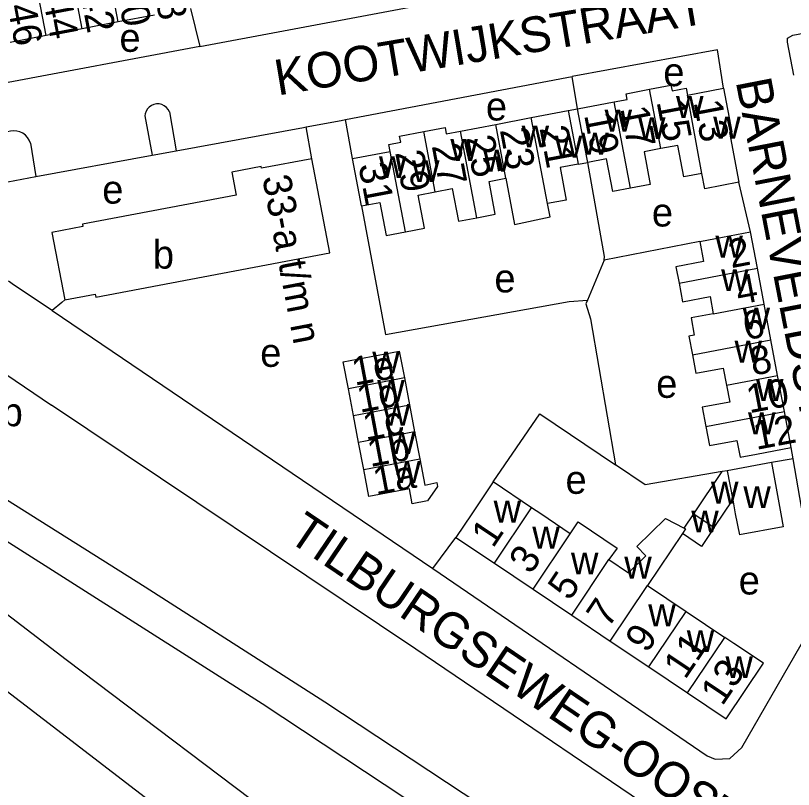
# Model space of a CAD drawing. Extents: x 158356 to 159894, y 383831 to 385260.
# Drawn here: x 158701.2 to 158810.6, y 383961.2 to 384070.1 of the extents above; entities that cross this region are included whole.
import ezdxf

# ---------------------------------------------------------------- set-up
doc = ezdxf.new("R2010")
doc.units = 0
for name, color, linetype in [('BLT_Basislijn', 7, 'Continuous'), ('BLT_Bebouwing', 7, 'Continuous'), ('BLT_Centroide', 7, 'Continuous'), ('BLT_Huisnummer', 7, 'Continuous'), ('BLT_Huisnummer_ tussenligend', 7, 'Continuous'), ('BLT_Huisnummer_reeks', 7, 'Continuous'), ('BLT_Onderdoorgang_en_onderverdeling', 7, 'Continuous'), ('BLT_Onderverdeling_panden', 7, 'Continuous'), ('BLT_Straatnaam', 7, 'Continuous')]:
    doc.layers.add(name, color=color, linetype=linetype)

msp = doc.modelspace()

# ---------------------------------------------------------------- linework, layer by layer
at = {"layer": 'BLT_Basislijn'}
for p, q in [((158727.11, 384065.73), (158770.26, 384073.85)), ((158725.81, 384071.1), (158727.11, 384065.73)), ((158727.11, 384065.73), (158694.69, 384059.64)), ((158780.27, 384056.96), (158779.51, 384061.52)), ((158722.83, 384056.55), (158723.81, 384051.07)), ((158719.39, 384056), (158720.43, 384050.45)), ((158748.6, 384049.99), (158747.61, 384055.47)), ((158742.89, 384049.96), (158742.08, 384054.43)), ((158703.31, 384052.16), (158704.05, 384047.44)), ((158720.43, 384050.45), (158723.81, 384051.07)), ((158704.05, 384047.44), (158720.43, 384050.45)), ((158699.14, 384046.54), (158704.05, 384047.44)), ((158804.58, 384039.65), (158802.96, 384046.65)), ((158797.44, 384038.29), (158783.99, 384035.69)), ((158783.99, 384035.69), (158781.64, 384030.04)), ((158677.95, 384034.41), (158706.27, 384015.3)), ((158706.34, 384028.61), (158759.91, 383992.3)), ((158719.42, 383989.69), (158667.79, 384022.18)), ((158733.69, 383949.17), (158656.47, 384008.34)), ((158810.59, 384007.75), (158810.32, 384009.33)), ((158810.59, 384007.75), (158807.52, 384007.22)), ((158813.96, 383988.01), (158810.59, 384007.75)), ((158789.78, 384004.07), (158785.59, 384006.9)), ((158800.61, 384005.94), (158789.78, 384004.07)), ((158759.91, 383992.3), (158763.12, 383996.69))]:
    msp.add_line(p, q, dxfattribs=at)
for points in [[(158810.66, 384061.72), (158809.81, 384066.33), (158809.81, 384066.91), (158810.54, 384067.32), (158847.76, 384074.35)], [(158800.8, 384059.86), (158799.92, 384065.26), (158779.51, 384061.52)], [(158747.61, 384055.47), (158778.74, 384061.38), (158779.51, 384061.52)], [(158722.83, 384056.55), (158722.65, 384056.88), (158722.41, 384057.17), (158722.11, 384057.4), (158721.77, 384057.57), (158721.4, 384057.66), (158721.03, 384057.67), (158720.65, 384057.6), (158720.31, 384057.45), (158720, 384057.23), (158719.74, 384056.96), (158719.55, 384056.63), (158719.43, 384056.28), (158719.39, 384056)], [(158742.08, 384054.43), (158746.98, 384055.34), (158747.61, 384055.47)], [(158723.81, 384051.07), (158741.69, 384054.36), (158742.08, 384054.43)], [(158703.31, 384052.16), (158703.13, 384052.57), (158702.88, 384052.95), (158702.57, 384053.27), (158702.21, 384053.53), (158701.81, 384053.73), (158701.38, 384053.85), (158700.93, 384053.89), (158700.48, 384053.85), (158700.05, 384053.73), (158699.65, 384053.54), (158699.28, 384053.28), (158698.97, 384052.96), (158698.72, 384052.58), (158698.54, 384052.17), (158698.44, 384051.74), (158698.42, 384051.29), (158698.46, 384050.9)], [(158783.99, 384035.69), (158784.03, 384036.22), (158781.7, 384049.42)], [(158749.86, 384043.31), (158753.23, 384025.24), (158779.09, 384029.87), (158781.64, 384030.04)], [(158706.34, 384028.61), (158701.03, 384032.11), (158700.18, 384032.75)], [(158708.12, 384030.1), (158707.7, 384029.75), (158706.34, 384028.61)], [(158781.64, 384030.04), (158781.43, 384029.54), (158782.1, 384027.44), (158785.59, 384006.9)], [(158735.9, 383973.27), (158664.77, 384018.5)], [(158658.2, 384017.9), (158708.3, 383979.52), (158740.71, 383955.02), (158752.16, 383946.49), (158811.09, 383902.1)], [(158845.77, 383924.27), (158815.12, 383942.93), (158798.74, 383953.03), (158757.49, 383980.97), (158706.27, 384015.3)], [(158768.38, 384004.49), (158774.94, 384014.07), (158785.59, 384006.9)], [(158759.91, 383992.3), (158798.47, 383965.97), (158799.62, 383965.5), (158801.69, 383965.58), (158803.35, 383967.13), (158814.2, 383985.93), (158813.96, 383988.01)], [(158848.65, 383902.86), (158801.74, 383935.63), (158773.98, 383954.21), (158744.72, 383973.5), (158719.42, 383989.69)], [(158848.91, 383896.59), (158784.62, 383941.05), (158735.9, 383973.27)]]:
    msp.add_lwpolyline(points, dxfattribs=at)
at = {"layer": 'BLT_Bebouwing'}
for p, q in [((158720.73, 384070.15), (158715.65, 384069.19)), ((158715.65, 384069.19), (158710.58, 384068.23)), ((158710.58, 384068.23), (158705.5, 384067.27)), ((158705.5, 384067.27), (158700.42, 384066.32)), ((158795.73, 384058.9), (158800.8, 384059.86)), ((158780.27, 384056.96), (158785.42, 384057.94)), ((158773.74, 384055.74), (158778.93, 384056.72)), ((158778.93, 384056.72), (158780.27, 384056.96)), ((158768.74, 384054.79), (158773.74, 384055.74)), ((158763.77, 384053.85), (158768.74, 384054.79)), ((158753.89, 384050.99), (158753.7, 384051.96)), ((158745.39, 384036.7), (158742.89, 384049.96)), ((158748.6, 384049.99), (158753.89, 384050.99)), ((158780.36, 384049.2), (158781.7, 384049.42)), ((158805.55, 384034.55), (158804.58, 384039.65)), ((158806.5, 384029.51), (158805.55, 384034.55)), ((158807.46, 384024.47), (158806.5, 384029.51)), ((158808.4, 384019.47), (158807.46, 384024.47)), ((158809.37, 384014.39), (158808.4, 384019.47)), ((158755.89, 384019.12), (158756.61, 384015.32)), ((158748.73, 384013.82), (158748.01, 384017.61)), ((158756.61, 384015.32), (158757.33, 384011.53)), ((158749.46, 384010.03), (158748.73, 384013.82)), ((158810.32, 384009.33), (158809.37, 384014.39)), ((158757.33, 384011.53), (158758.05, 384007.73)), ((158750.18, 384006.23), (158749.46, 384010.03)), ((158807.52, 384007.22), (158801.32, 384006.06)), ((158796.63, 384000), (158800.61, 384005.94)), ((158801.32, 384006.06), (158800.61, 384005.94)), ((158773.8, 384000.86), (158768.38, 384004.49)), ((158799.48, 383998.1), (158802.08, 384001.98)), ((158795.27, 383997.97), (158796.63, 384000)), ((158763.12, 383996.69), (158768.56, 383993.05)), ((158768.56, 383993.05), (158773.99, 383989.4)), ((158790.1, 383989.92), (158795.53, 383986.28)), ((158773.99, 383989.4), (158779.43, 383985.76)), ((158779.43, 383985.76), (158784.86, 383982.11)), ((158795.53, 383986.28), (158800.97, 383982.63)), ((158784.86, 383982.11), (158790.3, 383978.47)), ((158790.3, 383978.47), (158795.73, 383974.82))]:
    msp.add_line(p, q, dxfattribs=at)
for points in [[(158790.4, 384059.73), (158793.4, 384060.3), (158793.55, 384059.5), (158795.54, 384059.88), (158795.73, 384058.9)], [(158800.8, 384059.86), (158801.96, 384053.72), (158801.64, 384053.66), (158802.96, 384046.65)], [(158785.42, 384057.94), (158787.24, 384058.28), (158787.09, 384059.1), (158790.4, 384059.73)], [(158758.62, 384053.78), (158761.61, 384054.34), (158761.77, 384053.48), (158763.77, 384053.85)], [(158753.7, 384051.96), (158755.38, 384052.27), (158755.21, 384053.13), (158758.62, 384053.78)], [(158791.98, 384051.39), (158789.62, 384050.94), (158790.49, 384046.35), (158787.72, 384045.82)], [(158797.75, 384047.88), (158795.19, 384047.39), (158794.35, 384051.84), (158791.98, 384051.39)], [(158742.89, 384049.96), (158735.79, 384048.61), (158735.75, 384048.84), (158731.64, 384048.06), (158732.24, 384044.85), (158710.59, 384040.75), (158710.65, 384040.42), (158706.32, 384039.6), (158708.12, 384030.1)], [(158749.86, 384043.31), (158749.53, 384045.07), (158748.6, 384049.99)], [(158787.72, 384045.82), (158785.22, 384045.35), (158784.35, 384049.92), (158781.7, 384049.42)], [(158780.36, 384049.2), (158777.8, 384048.71), (158778.66, 384044.14), (158776.03, 384043.64)], [(158802.96, 384046.65), (158798.15, 384045.74), (158797.75, 384047.88)], [(158766.08, 384041.65), (158768.68, 384042.14), (158767.81, 384046.75), (158770.17, 384047.2)], [(158770.17, 384047.2), (158771.39, 384040.71), (158776.42, 384041.76), (158776.03, 384043.64)], [(158760.23, 384045.3), (158762.62, 384045.76), (158763.49, 384041.16), (158766.08, 384041.65)], [(158756.03, 384039.68), (158758.72, 384040.19), (158757.84, 384044.85), (158760.23, 384045.3)], [(158749.86, 384043.31), (158752.46, 384043.8), (158753.33, 384039.17), (158756.03, 384039.68)], [(158797.44, 384038.29), (158799.67, 384038.72), (158804.58, 384039.65)], [(158797.44, 384038.29), (158797.97, 384035.49), (158794.09, 384034.76), (158794.53, 384032.46)], [(158708.12, 384030.1), (158712.4, 384030.91), (158712.48, 384030.47), (158745.39, 384036.7)], [(158794.53, 384032.46), (158795.02, 384029.85), (158798.89, 384030.58), (158799.35, 384028.15)], [(158799.35, 384028.15), (158796.22, 384027.56), (158796.68, 384025.14), (158795.92, 384024.99), (158796.41, 384022.39)], [(158748.01, 384017.61), (158747.28, 384021.41), (158755.17, 384022.91), (158755.89, 384019.12)], [(158796.41, 384022.39), (158796.91, 384019.78), (158800.76, 384020.51), (158801.21, 384018.11)], [(158801.21, 384018.11), (158801.67, 384015.72), (158797.8, 384014.99), (158798.31, 384012.3)], [(158798.31, 384012.3), (158798.82, 384009.6), (158802.67, 384010.33), (158803.12, 384007.97), (158805.41, 384008.41), (158810.32, 384009.33)], [(158758.05, 384007.73), (158758.75, 384004.06), (158760.45, 384004.4), (158760.55, 384003.87), (158759.15, 384001.82), (158757.01, 384001.4), (158756.6, 384003.52), (158750.91, 384002.44), (158750.18, 384006.23)], [(158807.52, 384007.22), (158808.87, 384000.01), (158809.2, 383998.18), (158803.05, 383997.04)], [(158768.38, 384004.49), (158765.93, 384000.83), (158765.36, 383999.99), (158763.12, 383996.69)], [(158802.08, 384001.98), (158802.45, 384000), (158803.05, 383997.04)], [(158779.23, 383997.21), (158775.08, 384000), (158773.8, 384000.86)], [(158779.23, 383997.21), (158780.32, 383998.86), (158785.83, 383995.2), (158784.67, 383993.57)], [(158784.67, 383993.57), (158787.42, 383991.7), (158789.87, 383994.11), (158788.61, 383995.39), (158792.62, 383999.33), (158795.27, 383997.97)], [(158799.48, 383998.1), (158797.68, 383995.43), (158795, 383997.22)], [(158795, 383997.22), (158790.1, 383989.92)], [(158795.73, 383974.82), (158801.17, 383971.17), (158806.4, 383978.98), (158802.25, 383981.77), (158800.97, 383982.63)]]:
    msp.add_lwpolyline(points, dxfattribs=at)
at = {"layer": 'BLT_Onderdoorgang_en_onderverdeling'}
for points in [[(158778.93, 384056.72), (158779.86, 384051.81), (158780.36, 384049.2)], [(158781.7, 384049.42), (158781.2, 384052.05), (158780.27, 384056.96)]]:
    msp.add_lwpolyline(points, dxfattribs=at)
at = {"layer": 'BLT_Onderverdeling_panden'}
for p, q in [((158710.58, 384068.23), (158708.35, 384080.01)), ((158715.65, 384069.19), (158714.28, 384076.26)), ((158705.5, 384067.27), (158704.16, 384074.35)), ((158791.98, 384051.39), (158790.4, 384059.73)), ((158787.72, 384045.82), (158785.42, 384057.94)), ((158776.03, 384043.64), (158773.74, 384055.74)), ((158770.17, 384047.2), (158768.74, 384054.79)), ((158760.23, 384045.3), (158758.62, 384053.78)), ((158766.08, 384041.65), (158763.77, 384053.85)), ((158756.03, 384039.68), (158753.89, 384050.99)), ((158794.53, 384032.46), (158805.55, 384034.55)), ((158799.35, 384028.15), (158806.5, 384029.51)), ((158796.41, 384022.39), (158807.46, 384024.47)), ((158801.21, 384018.11), (158808.4, 384019.47)), ((158755.89, 384019.12), (158748.01, 384017.61)), ((158748.73, 384013.82), (158756.61, 384015.32)), ((158798.31, 384012.3), (158809.37, 384014.39)), ((158757.33, 384011.53), (158749.46, 384010.03)), ((158750.18, 384006.23), (158758.05, 384007.73)), ((158801.32, 384006.06), (158802.08, 384001.98)), ((158768.56, 383993.05), (158773.8, 384000.86)), ((158796.63, 384000), (158799.48, 383998.1)), ((158773.99, 383989.4), (158779.23, 383997.21)), ((158779.43, 383985.76), (158784.67, 383993.57)), ((158784.86, 383982.11), (158790.1, 383989.92)), ((158790.3, 383978.47), (158795.53, 383986.28)), ((158795.73, 383974.82), (158800.97, 383982.63))]:
    msp.add_line(p, q, dxfattribs=at)
for points in [[(158797.75, 384047.88), (158795.73, 384058.9)], [(158795.27, 383997.97), (158795.44, 383997.88), (158795, 383997.22)]]:
    msp.add_lwpolyline(points, dxfattribs=at)

# ---------------------------------------------------------------- texts
at = {"layer": 'BLT_Centroide'}
for s, p in [('e', (158715.81, 384064.99)), ('e', (158792.32, 384060.16)), ('w', (158794.11, 384055.69)), ('e', (158767.36, 384055.33)), ('w', (158784.06, 384053.78)), ('w', (158788.77, 384052.73)), ('w', (158799.34, 384052.78)), ('w', (158772.39, 384051.55)), ('w', (158777.05, 384050.11)), ('w', (158780.77, 384050.53)), ('w', (158762.36, 384049.66)), ('w', (158766.97, 384048.14)), ('w', (158752.31, 384047.23)), ('w', (158756.97, 384046.66)), ('e', (158713.39, 384043.64)), ('e', (158790.71, 384040.42)), ('w', (158799.65, 384036.06)), ('b', (158720.51, 384034.5)), ('e', (158768.56, 384031.15)), ('w', (158800.45, 384031.34)), ('w', (158803.47, 384025.94)), ('e', (158735.61, 384020.68)), ('w', (158802.34, 384021.28)), ('w', (158751.38, 384019.75)), ('e', (158791.32, 384016.32)), ('w', (158752.07, 384015.78)), ('w', (158805.36, 384015.88)), ('p', (158699.24, 384012.33)), ('w', (158752.86, 384012.4)), ('w', (158804.24, 384011.19)), ('w', (158753.6, 384008.43)), ('w', (158754.34, 384004.36)), ('e', (158778.56, 384002.82)), ('w', (158799.03, 384001.45)), ('w', (158803.58, 384000.82)), ('w', (158768.45, 383998.78)), ('w', (158796.25, 383997.39)), ('w', (158773.89, 383995.12)), ('w', (158779.33, 383991.48)), ('w', (158786.83, 383990.91)), ('e', (158802.93, 383988.66)), ('w', (158790.2, 383984.19)), ('w', (158795.62, 383980.55)), ('w', (158801.06, 383976.91))]:
    msp.add_text(s, height=4, dxfattribs=at).set_placement(p)
at = {"layer": 'BLT_Huisnummer'}
for s, rotation, p in [('38', 280.6809, (158720.39, 384075.07)), ('42', 280.6809, (158710.26, 384073.29)), ('13', 280.7224, (158796.57, 384057.91)), ('19', 280.7224, (158781.17, 384056.11)), ('21', 280.7224, (158774.89, 384054.27)), ('25', 280.7224, (158764.53, 384052.93)), ('31', 280.7224, (158749.41, 384049.06)), ('2', 10.7217, (158801.88, 384034.55)), ('6', 10.7217, (158803.92, 384024.41)), ('1e', 10.7217, (158748.9, 384018.02)), ('1c', 10.7217, (158750.46, 384010.29)), ('12', 10.7217, (158805.39, 384008.99)), ('1a', 10.7217, (158751.89, 384002.62)), ('1', 56.1426, (158768.36, 383995.06)), ('5', 56.1426, (158779.13, 383987.63)), ('9', 56.1426, (158790.01, 383980.28)), ('13', 56.1426, (158800.62, 383972.85))]:
    msp.add_text(s, height=4, rotation=rotation, dxfattribs=at).set_placement(p)
at = {"layer": 'BLT_Huisnummer_ tussenligend'}
for s, rotation, p in [('40', 280.6809, (158715.31, 384074.14)), ('44', 280.6809, (158705.06, 384072.4)), ('46', 280.6809, (158700.05, 384071.43)), ('15', 280.7224, (158791.36, 384057.97)), ('17', 280.7224, (158786.26, 384057.05)), ('23', 280.7224, (158769.31, 384054.01)), ('29', 280.7224, (158754.58, 384050.83)), ('27', 280.7224, (158759.73, 384051.77)), ('4', 10.7217, (158802.92, 384029.4)), ('8', 10.7217, (158804.92, 384019.43)), ('1d', 10.7217, (158749.63, 384014.2)), ('10', 10.7217, (158804.41, 384014.14)), ('1b', 10.7217, (158751.09, 384006.57)), ('3', 56.1426, (158773.66, 383991.35)), ('7', 56.1426, (158784.57, 383983.81)), ('11', 56.1426, (158795.4, 383976.58))]:
    msp.add_text(s, height=4, rotation=rotation, dxfattribs=at).set_placement(p)
at = {"layer": 'BLT_Huisnummer_reeks'}
msp.add_text('33-a t/m n', height=4, rotation=280.7224, dxfattribs=at).set_placement((158735.88, 384047.34))
at = {"layer": 'BLT_Straatnaam'}
for s, height, rotation, p in [('KOOTWIJKSTRAAT', 5, 9.554, (158738.09, 384058.84)), ('BARNEVELDSTRAAT', 4.9999, 281, (158802.49, 384060.84)), ('TILBURGSEWEG-OOST', 4.9999, 325.862, (158739.25, 383996.39))]:
    msp.add_text(s, height=height, rotation=rotation, dxfattribs=at).set_placement(p)

doc.saveas('drawing.dxf')
